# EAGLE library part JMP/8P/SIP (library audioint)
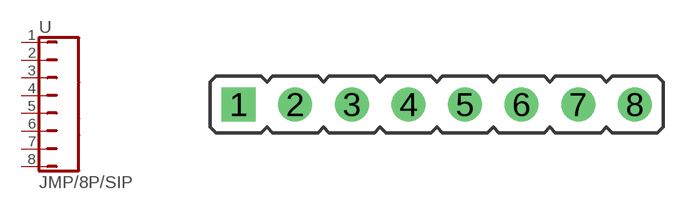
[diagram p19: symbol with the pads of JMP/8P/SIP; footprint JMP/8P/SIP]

Designator prefix -

## JMP/8P/SIP  [JMP/8P/SIP]
1  1  pas
2  2  pas
3  3  pas
4  4  pas
5  5  pas
6  6  pas
7  7  pas
8  8  pas

## Footprint JMP/8P/SIP (pad centres in mm)
drill 0.914 pad 1.524 square: 1 -8.89,0
drill 0.914 pad 1.524 round: 2 -6.35,0; 3 -3.81,0; 4 -1.27,0; 5 1.27,0; 6 3.81,0; 7 6.35,0; 8 8.89,0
